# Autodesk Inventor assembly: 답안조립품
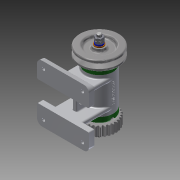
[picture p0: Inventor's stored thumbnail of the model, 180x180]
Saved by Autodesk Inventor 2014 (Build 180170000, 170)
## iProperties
Created: 2016-07
Part Number: 답안조립품
Document SubType Name: Assembly
Designer: user
Author: user
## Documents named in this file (13)
- C:\Users\user\Desktop\460708V1029\답안조립품.iam
- C:\Users\user\Desktop\460708V1029\본체.ipt
- C:\Users\user\Desktop\460708V1029\커버.ipt
- C:\Users\user\Desktop\460708V1029\축.ipt
- C:\Users\user\Desktop\460708V1029\키 3 x 3 x 12.ipt
- C:\Users\user\Desktop\460708V1029\V벨트풀리.ipt
- C:\Users\user\Desktop\460708V1029\스퍼기어.ipt
- C:\Users\user\Desktop\460708V1029\와셔 8x17.ipt
- C:\Users\user\Desktop\460708V1029\스프링와셔 8.ipt
- C:\Users\user\Desktop\460708V1029\너트 M 8.ipt
- C:\Users\user\Desktop\460708V1029\볼트 M4 x 12.ipt
- C:\Users\user\Desktop\460708V1029\오일 실 15 25 7.ipt
- C:\Users\user\Desktop\460708V1029\베어링 15 x 32 x 9.ipt
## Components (11 placed, 3 different names)
1. V벨트풀리:1 — Mate:5, Mate:6, Insert:5, Insert:11
2. KS B 2023 6002 - 15 x 32 x 9:1 — Insert:17
3. KS B 2023 6002 - 15 x 32 x 9:2 — Insert:18, Insert:21
4. ISO 4762 M4 x 12:1 — Insert:15
5. ISO 4762 M4 x 12:3
6. ISO 4762 M4 x 12:4
7. ISO 4762 M4 x 12:5
8. ISO 4762 M4 x 12:2 — Insert:16
9. ISO 4762 M4 x 12:6
10. ISO 4762 M4 x 12:7
11. ISO 4762 M4 x 12:8
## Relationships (9: Insert 7, Mate 2)
- Mate:5: V벨트풀리:1
- Mate:6: V벨트풀리:1
- Insert:5: V벨트풀리:1
- Insert:11: V벨트풀리:1
- Insert:15: ISO 4762 M4 x 12:1
- Insert:16: ISO 4762 M4 x 12:2
- Insert:17: KS B 2023 6002 - 15 x 32 x 9:1
- Insert:18: KS B 2023 6002 - 15 x 32 x 9:2
- Insert:21: KS B 2023 6002 - 15 x 32 x 9:2
